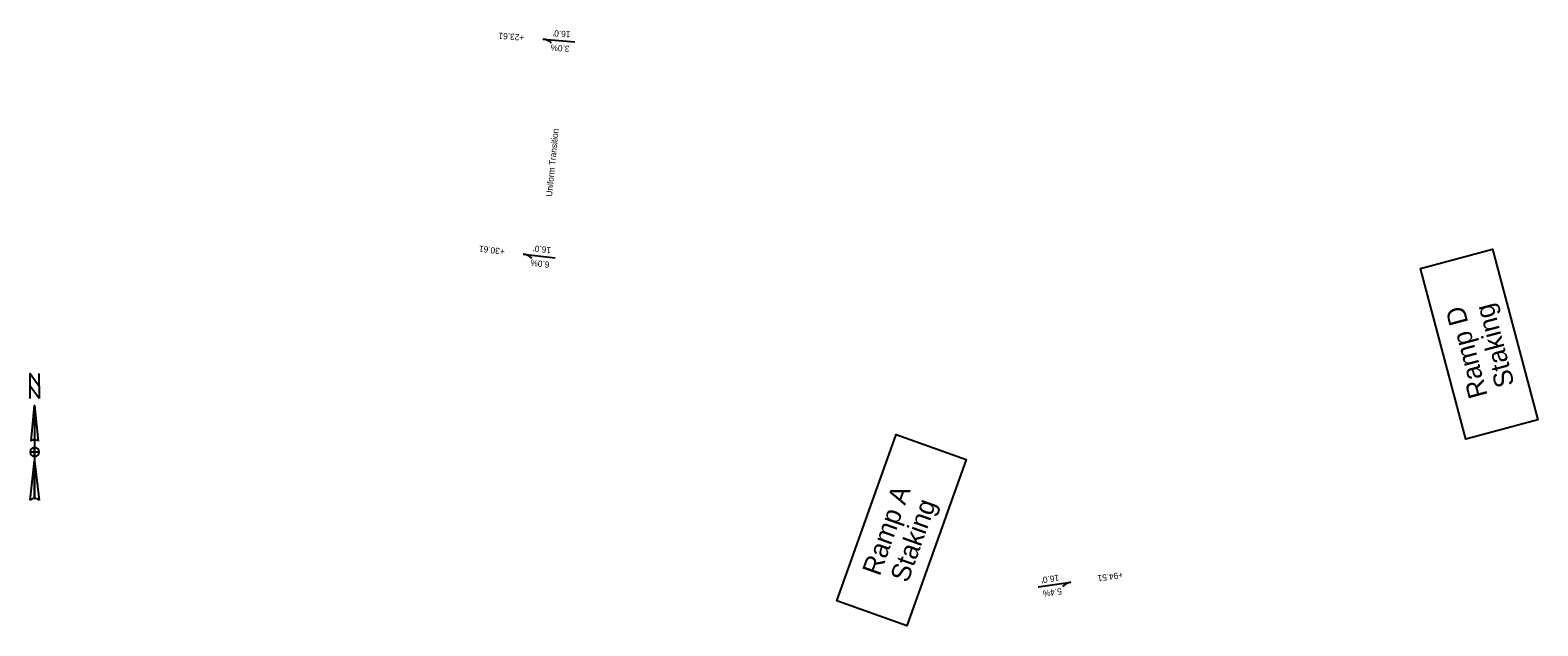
# Model space of a CAD drawing. Extents: x 20506035 to 20507470, y 7969245 to 7972296.
# Drawn here: x 20506343 to 20506986, y 7971577 to 7971831 of the extents above; entities that cross this region are included whole.
import ezdxf

# ---------------------------------------------------------------- set-up
doc = ezdxf.new("R2010")
doc.units = 0
for name, color, linetype in [('_CIVIL_CONSTRUCTION', 7, 'Continuous'), ('EdgeShoulder', 7, 'Continuous'), ('Joints', 7, 'Continuous')]:
    doc.layers.add(name, color=color, linetype=linetype)

msp = doc.modelspace()

# ---------------------------------------------------------------- linework, layer by layer
at = {"layer": '_CIVIL_CONSTRUCTION'}
for p, q in [((20506561.32, 7971827.35), (20506574.93, 7971826.27)), ((20506552.93, 7971735.74), (20506566.48, 7971734.1)), ((20506772.67, 7971593.75), (20506786.5, 7971595.73))]:
    msp.add_line(p, q, dxfattribs=at)
for points in [[(20506966.41, 7971737.79), (20506985.8, 7971665.02), (20506955.07, 7971656.83), (20506935.68, 7971729.6)], [(20506955.07, 7971656.83), (20506935.68, 7971729.6), (20506966.41, 7971737.79), (20506985.8, 7971665.02)]]:
    msp.add_lwpolyline(points, close=True, dxfattribs=at)
for centre, start, end in [((20506560.83, 7971821.2), 47.28593, 85.43658), ((20506552.18, 7971729.62), 44.92702, 83.07767), ((20506787.37, 7971589.62), 98.10253, 136.30557)]:
    msp.add_arc(centre, 6.16, start, end, dxfattribs=at)
at = {"layer": 'EdgeShoulder'}
for p, q in [((20506344.42, 7971671.07), (20506345.94, 7971655.85)), ((20506344.42, 7971671.07), (20506344.42, 7971631.51)), ((20506342.89, 7971655.85), (20506342.89, 7971655.85)), ((20506342.95, 7971656), (20506343.24, 7971656.31)), ((20506342.51, 7971630.75), (20506344.42, 7971647.49)), ((20506344.42, 7971649.39), (20506344.42, 7971649.39))]:
    msp.add_line(p, q, dxfattribs=at)
msp.add_lwpolyline([(20506346.32, 7971674.11), (20506342.51, 7971679.43), (20506342.51, 7971684.76), (20506346.32, 7971679.43)], close=True, dxfattribs=at)
for points in [[(20506342.51, 7971674.11), (20506342.51, 7971684.76), (20506346.32, 7971679.43), (20506346.32, 7971684.76)], [(20506342.89, 7971655.85), (20506344.42, 7971671.07), (20506344.42, 7971656.62)], [(20506344.42, 7971649.39), (20506344.42, 7971651.29), (20506342.51, 7971651.29)], [(20506346.32, 7971651.29), (20506344.42, 7971651.29), (20506344.42, 7971653.19)], [(20506344.42, 7971631.51), (20506344.42, 7971647.49), (20506346.32, 7971630.75)]]:
    msp.add_lwpolyline(points, dxfattribs=at)
for centre, radius, start, end in [((20506344.42, 7971651.29), 1.9, 90, 180), ((20506344.42, 7971651.29), 1.9, 180, 270), ((20506344.42, 7971654.71), 1.9, 90.02039, 143.12574), ((20506344.42, 7971654.71), 1.9, 36.84806, 90.02184), ((20506344.42, 7971651.29), 1.9, 0, 90), ((20506344.42, 7971651.29), 1.9, 270, 360), ((20506344.41, 7971628.76), 2.76, 89.98939, 133.61895), ((20506344.42, 7971628.76), 2.76, 46.40206, 90.00064)]:
    msp.add_arc(centre, radius, start, end, dxfattribs=at)
at = {"layer": 'Joints'}
for points in [[(20506741.91, 7971648.09), (20506716.61, 7971577.15), (20506686.65, 7971587.84), (20506711.96, 7971658.78)], [(20506686.65, 7971587.84), (20506711.96, 7971658.78), (20506741.91, 7971648.09), (20506716.61, 7971577.15)]]:
    msp.add_lwpolyline(points, close=True, dxfattribs=at)

# ---------------------------------------------------------------- texts
at = {"layer": '_CIVIL_CONSTRUCTION'}
for s, height, rotation, p in [("16.0'", 2.664, 175.56544, (20506573.14, 7971830.68)), ('+23.61', 2.664, 175.46271, (20506553.43, 7971829.31)), ('3.0%', 2.664, 175.56544, (20506572.74, 7971824.51)), ('Uniform Transition', 2.664, 84.38599, (20506565.19, 7971760.12)), ('+30.61', 2.664, 173.1038, (20506545.12, 7971738.02)), ("16.0'", 2.664, 173.20652, (20506564.87, 7971738.59)), ('6.0%', 2.664, 173.20652, (20506564.21, 7971732.44)), ('Staking', 8.16, 104.92297, (20506975.9, 7971680.06)), ('Ramp D', 8.16, 104.92297, (20506964.46, 7971675.44)), ('+94.51', 2.664, 188.12879, (20506808.68, 7971600.24)), ("16.0'", 2.664, 188.23151, (20506781.29, 7971598.99)), ('5.4%', 2.664, 188.23151, (20506782.48, 7971593.3))]:
    msp.add_text(s, height=height, rotation=rotation, dxfattribs=at).set_placement(p)
at = {"layer": 'Joints'}
for s, p in [('Ramp A', (20506705.01, 7971598.03)), ('Staking', (20506716.98, 7971595.16))]:
    msp.add_text(s, height=8.16, rotation=70.3655, dxfattribs=at).set_placement(p)

doc.saveas('drawing.dxf')
